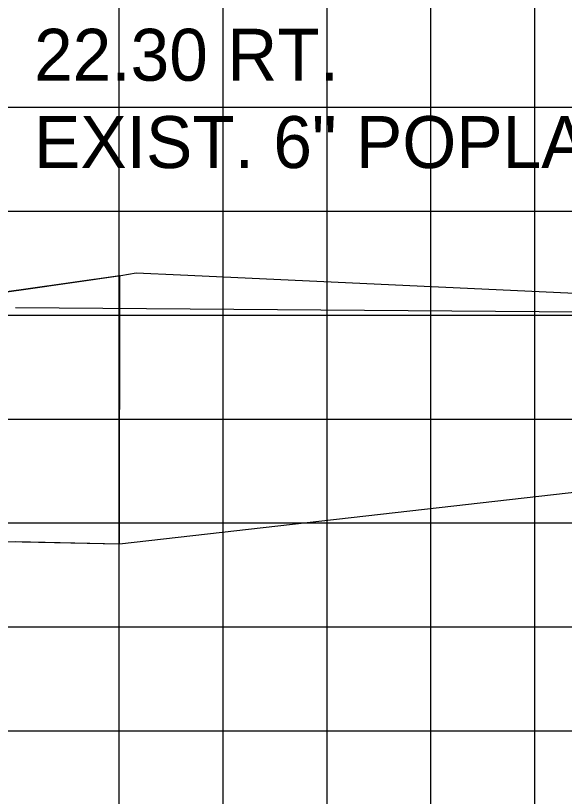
# Model space of a CAD drawing. Extents: x 859129 to 859299, y 366268 to 366378.
# Drawn here: x 859227.46 to 859232.75, y 366343.61 to 366351.12 of the extents above; entities that cross this region are included whole.
import ezdxf

# ---------------------------------------------------------------- set-up
doc = ezdxf.new("R2010")
doc.units = 0
for name, color, linetype in [('D_Roadway_Drive_Gravel_RT', 7, 'Continuous'), ('D_Roadway_Drive_SubGrade', 7, 'Continuous'), ('D_Text_Monospaced', 7, 'Continuous'), ('JUNK COM EXC', 7, 'Continuous'), ('MAJOR', 7, 'Continuous'), ('MINOR', 7, 'Continuous'), ('S_Roadway_Centerline', 7, 'Continuous')]:
    doc.layers.add(name, color=color, linetype=linetype)

msp = doc.modelspace()

# ---------------------------------------------------------------- linework, layer by layer
at = {"layer": 'D_Roadway_Drive_Gravel_RT'}
msp.add_line((859227.4637, 366348.3106), (859237.51, 366348.2307), dxfattribs=at)
at = {"layer": 'D_Roadway_Drive_SubGrade'}
for p, q in [((859228.4638, 366346.0371), (859237.51, 366347.0639)), ((859227.4638, 366346.0571), (859228.4638, 366346.0371))]:
    msp.add_line(p, q, dxfattribs=at)
at = {"layer": 'JUNK COM EXC'}
msp.add_lwpolyline([(859196.4619, 366348.151), (859196.4619, 366346.0372), (859201.4619, 366346.1372), (859212.4619, 366346.3572), (859223.4619, 366346.1372), (859228.4638, 366346.0371), (859228.4658, 366348.6142), (859227.5388, 366348.4815), (859226.0517, 366348.2784), (859225.9539, 366348.2637), (859225.2744, 366348.2511), (859225.1063, 366348.2199), (859222.8924, 366348.2618), (859222.4561, 366348.2516), (859214.7027, 366348.3764), (859213.2546, 366348.4147), (859210.8671, 366348.3828), (859201.9564, 366348.3079), (859200.2111, 366348.2663), (859197.4051, 366348.1943), (859196.4619, 366348.151)], dxfattribs=at)
at = {"layer": 'MAJOR'}
for p, q in [((859232.4616, 366337.2365), (859232.4616, 366357.2365)), ((859142.4616, 366347.2365), (859282.4616, 366347.2365))]:
    msp.add_line(p, q, dxfattribs=at)
at = {"layer": 'MINOR'}
for p, q in [((859228.4616, 366337.2365), (859228.4616, 366357.2365)), ((859229.4616, 366337.2365), (859229.4616, 366357.2365)), ((859230.4616, 366337.2365), (859230.4616, 366357.2365)), ((859231.4616, 366337.2365), (859231.4616, 366357.2365)), ((859142.4616, 366350.2365), (859282.4616, 366350.2365)), ((859142.4616, 366349.2365), (859282.4616, 366349.2365)), ((859142.4616, 366348.2365), (859282.4616, 366348.2365)), ((859142.4616, 366346.2365), (859282.4616, 366346.2365)), ((859142.4616, 366345.2365), (859282.4616, 366345.2365)), ((859142.4616, 366344.2365), (859282.4616, 366344.2365))]:
    msp.add_line(p, q, dxfattribs=at)
at = {"layer": 'S_Roadway_Centerline'}
msp.add_lwpolyline([(859169.3533, 366346.9932), (859173.6101, 366346.8832), (859175.6578, 366347.0106), (859183.0249, 366347.2302), (859192.8284, 366347.9692), (859193.4049, 366348.0105), (859197.4051, 366348.1943), (859200.2111, 366348.2663), (859201.9564, 366348.3079), (859210.8671, 366348.3828), (859213.2546, 366348.4147), (859214.7027, 366348.3764), (859222.4561, 366348.2516), (859222.8924, 366348.2618), (859225.1063, 366348.2199), (859225.2744, 366348.2511), (859225.9539, 366348.2637), (859226.0517, 366348.2784), (859227.5388, 366348.4815), (859228.4779, 366348.616), (859228.6251, 366348.6431), (859229.0512, 366348.6226), (859249.6219, 366347.6694)], dxfattribs=at)

# ---------------------------------------------------------------- texts
at = {"layer": 'D_Text_Monospaced'}
for s, p in [('22.30 RT.', (859227.6411, 366350.4905)), ('EXIST. 6" POPLAR', (859227.6411, 366349.6505))]:
    msp.add_text(s, height=0.49998, dxfattribs=at).set_placement(p)

doc.saveas('drawing.dxf')
